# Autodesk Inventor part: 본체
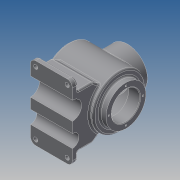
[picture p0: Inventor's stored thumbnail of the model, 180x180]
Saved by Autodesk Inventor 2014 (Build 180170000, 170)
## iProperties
Created: 2018-08
Part Number: 본체
Material: Generic
Document SubType Name: Modeling
Designer: kb542
Density: 1 g/cm^3
Appearance: Default
Author: kb542
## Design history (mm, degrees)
sketch "스케치1"
  geometry: L1 (0, 0)-(120, 0); L2 (0, 27)-(22, 27); L3 (22, 27)-(22, 37); L4 (25, 40)-(100.125, 40); L5 (0, 27)-(0, 38); L6 (0, 38)-(12, 38); L7 (12, 38)-(12, 50); L8 (12, 50)-(108.671, 50); A1 r 116 centre (4, 0) between (120, 0) and (108.671, 50); A2 r 106 centre (4, 0) between (110, 0) and (102.925, 38.078); A3 r 3 centre (25, 37) between (25, 40) and (22, 37); A4 r 3 centre (100.125, 37) between (102.925, 38.078) and (100.125, 40); 2 further points
  constraints: 16 end point, 9 point on circle, 4 centre point, 4 parallel, 4 point on line, 4 tangent, 3 perpendicular, 1 coincident, 1 equal radius, 1 horizontal, 1 horizontal alignment, 1 vertical alignment
  dimensions: "d17" = 120 distance of L1.start L1.end; "d18" = 116 radius of A1; "d20" = 108 distance from line of L7 L1.end; "d21" = 100 diameter of L8 L1; "d22" = 76 diameter of L6 L1; "d23" = 54 diameter of L2 L1; "d24" = 22 distance of L2.start L2.end; "d25" = 80 diameter of L4 L1; "d26" = 10 radial gap between concentric circles of A1 A2; "d78" = 3 radius of A3
revolve "회전2" sketch "스케치1" stored, may be unused: angle "d27" = 90 deg
node "작업 평면3"
sketch "스케치3"
  geometry: L1 (-70, -72)-(70, -72); L2 (70, -72)-(70, -82); L3 (70, -82)-(-70, -82); L4 (-70, -82)-(-70, -72); 2 further points
  constraints: 8 end point, 2 parallel, 1 horizontal, 1 midpoint, 1 perpendicular, 1 vertical alignment
  dimensions: "d29" = 82 distance from line of L3 point (0, 0); "d30" = 10 distance of L1.end L2.end; "d31" = 140 distance of L2.end L3.end
extrude "돌출2" join sketch "스케치3" distance "d32" = 80; taper "d33" = 0 deg
node "작업 평면4"
sketch "스케치4"
  geometry: L1 (-70, -72)-(70, -72) reference; L2 (0, 0)-(0, -72); L3 (-70, -82)-(-70, -72) reference; L4 (-50, -72)-(-50, -43.437); L5 (-50, -43.437)-(-40.304, -29.59); L6 (50, -43.437)-(40.304, -29.59); L7 (50, -72)-(50, -43.437); L8 (-50, -72)-(50, -72); L9 (-50, -43.437)-(-70, -72); A1 r 50 centre (0, 0) between (-40.304, -29.59) and (40.304, -29.59); 1 further point
  constraints: 14 end point, 3 symmetric about line, 2 collinear, 2 point on circle, 1 centre point, 1 midpoint, 1 parallel, 1 point on line, 3 other
  dimensions: "d37" = 20 distance between parallel lines of L3 L4; "d38" = 35 deg angle of L3 L5
extrude "돌출3" join sketch "스케치4" stored distance "d39" = 80; taper "d40" = 0 deg
sketch "스케치5"
  geometry: L1 (-70, -82)-(70, -82) reference; L2 (0, 0)-(0, -82); L3 (-70, -82)-(70, -82) reference; C1 r 50 at (0, 0) reference; C2 r 12.5 at (-27.5, -82); C3 r 17.5 at (22.5, -82)
  constraints: 2 centre point, 2 end point, 2 point on line, 1 midpoint
  dimensions: "d41" = 27.5 distance from line of C2.centre L2; "d42" = 22.5 distance from line of C3.centre L2; "d44" = 12.5 radius of C2; "d45" = 17.5 radius of C3
extrude "돌출4" cut sketch "스케치5" stored distance "d46" = 80; taper "d47" = 0 deg
node "작업 평면5"
sketch "스케치6"
  geometry: L1 (-88, 20)-(-88, 120) reference; C1 r 38 at (-38, 70); 1 further point
  constraints: 1 centre point, 1 horizontal alignment
  dimensions: "d49" = 76 diameter of C1; "d50" = 50 distance from line of L1 C1.centre
extrude "돌출5" join sketch "스케치6" stored distance "d51" = 80; taper "d52" = 0 deg
sketch "스케치7"
  geometry: C1 r 38 at (0, 0) reference; C2 r 27 at (0, 0); 1 further point
  constraints: 1 centre point, 1 coincident
  dimensions: "d53" = 54 diameter of C2
extrude "돌출6" cut sketch "스케치7" stored distance "d54" = 80; taper "d55" = 0 deg
sketch "스케치8" dims "d56" = 65
  geometry: C1 r 27 at (0, 0) reference; C2 r 38 at (0, 0) reference; 3 further points
  constraints: 2 horizontal alignment, 1 coincident, 2 other
hole "구멍1" sketch "스케치8" at (-32.5, 0) diameter "d57" = 3.242; stored, may be unused: countersink angle "d61" = 90 deg, drill point angle "d63" = 118 deg; dims "d58" = 8, "d59" = 4, "d60" = 2, "d62" = 10
sketch "스케치9" dims "d67" = 65
  geometry: C1 r 38 at (0, 0) reference; C2 r 27 at (0, 0) reference; 2 further points
  constraints: 2 vertical alignment, 1 coincident, 2 other
hole "구멍2" sketch "스케치9" at (0, 32.5) diameter "d68" = 3.242; stored, may be unused: countersink angle "d72" = 90 deg, drill point angle "d74" = 118 deg; dims "d69" = 8, "d70" = 4, "d71" = 2, "d73" = 10
fillet "모깎기1" dims "d79" = 10
hole "구멍3" diameter "d82" = 8; stored, may be unused: countersink angle "d86" = 90 deg, drill point angle "d88" = 118 deg; dims "d80" = 10, "d81" = 10, "d83" = 8, "d84" = 4, "d85" = 2, "d87" = 10
hole "구멍4" diameter "d91" = 8; stored, may be unused: countersink angle "d95" = 90 deg, drill point angle "d97" = 118 deg; dims "d89" = 10, "d90" = 10, "d92" = 8, "d93" = 4, "d94" = 2, "d96" = 10
hole "구멍5" diameter "d100" = 8; stored, may be unused: countersink angle "d104" = 90 deg, drill point angle "d106" = 118 deg; dims "d98" = 10, "d99" = 10, "d101" = 8, "d102" = 4, "d103" = 2, "d105" = 10
hole "구멍6" diameter "d109" = 8; stored, may be unused: countersink angle "d113" = 90 deg, drill point angle "d115" = 118 deg; dims "d107" = 10, "d108" = 10, "d110" = 8, "d111" = 4, "d112" = 2, "d114" = 10
chamfer "모따기1" distance "d116" = 1; stored, may be unused: second distance "d117" = 2, angle "d118" = 45 deg
chamfer "모따기2" distance "d119" = 1; stored, may be unused: second distance "d120" = 2, angle "d121" = 45 deg
fillet "모깎기2" dims "d122" = 3
fillet "모깎기3" dims "d123" = 3
fillet "모깎기4" dims "d124" = 3
fillet "모깎기5" dims "d125" = 3
fillet "모깎기6" dims "d126" = 3
fillet "모깎기7" dims "d127" = 3
fillet "모깎기8" dims "d128" = 3
node "작업 평면6"
sketch "스케치10"
  geometry: C1 r 32.5 at (0, 0); 1 further point
  constraints: 1 centre point, 1 coincident, 1 other
  dimensions: "d130" = 65 diameter of C1
feature "엠보싱1" sketch "스케치10" dims "d17" = 120, "d18" = 116, "d20" = 108, "d21" = 100, "d22" = 76, "d23" = 54, "d24" = 22, "d25" = 80, "d26" = 10, "d29" = 82, "d78" = 3, "d131" = 0.5, "d132" = 0
fillet "모깎기9" dims "d133" = 3
node "솔리드2"
pattern_circular "원형 패턴1" dims angle "d65" = 360 deg
pattern_circular "원형 패턴2" dims angle "d76" = 360 deg
other parameters: "d28" = -8, "d48" = -147, "d129" = -131.5
